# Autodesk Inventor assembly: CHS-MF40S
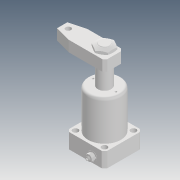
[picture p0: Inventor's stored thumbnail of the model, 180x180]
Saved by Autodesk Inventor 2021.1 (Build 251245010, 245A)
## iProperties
Created: 2019-04
Part Number: CHS-MF40S
Description: STEP AP203
Document SubType Name: Assembly
Designer: user
Title: chs-mf40s_asm.STEP
Revision Number: ÈÎºÎ
Sending System: SolidWorks 2017
Preprocessor: SwSTEP 2.0
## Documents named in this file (9)
- D:\Vault_2016\Projekty\Clamptek\Hydraulic\CHS\CHS-40\Inventor\CHS-MF40S\CHS-MF40S.iam
- D:\Vault_2016\Projekty\Clamptek\Hydraulic\CHS\CHS-40\Inventor\CHS-MF40S\CHS-MF40-03.ipt
- D:\Vault_2016\Projekty\Clamptek\Hydraulic\CHS\CHS-40\Inventor\CHS-MF40S\CHS-40S-02_5_1.ipt
- D:\Vault_2016\Projekty\Clamptek\Hydraulic\CHS\CHS-40\Inventor\CHS-MF40S\CHS-40S-01_5.ipt
- D:\Vault_2016\Projekty\Clamptek\Hydraulic\CHS\CHS-40\Inventor\CHS-MF40S\M18_5.ipt
- D:\Vault_2016\Projekty\Clamptek\Hydraulic\CHS\CHS-40\Inventor\CHS-MF40S\CHS-TXF-01_1.ipt
- D:\Vault_2016\Projekty\Clamptek\Hydraulic\CHS\CHS-40\Inventor\CHS-MF40S\CHS-MF40-TXF-03_1.ipt
- D:\Vault_2016\Projekty\Clamptek\Hydraulic\CHS\CHS-40\Inventor\CHS-MF40S\CHS-MF40-TXF-02_1.ipt
- D:\Vault_2016\Projekty\Clamptek\Hydraulic\CHS\CHS-40\Inventor\CHS-MF40S\M6_1.ipt
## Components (8 placed, 8 different names)
1. CHS-MF40-03_1
2. CHS-40S-02_5_1_2
3. CHS-40S-01_5_3
4. M18_5_4
5. CHS-TXF-01_1_5
6. CHS-MF40-TXF-03_1_6
7. CHS-MF40-TXF-02_1_7
8. M6_1_8
